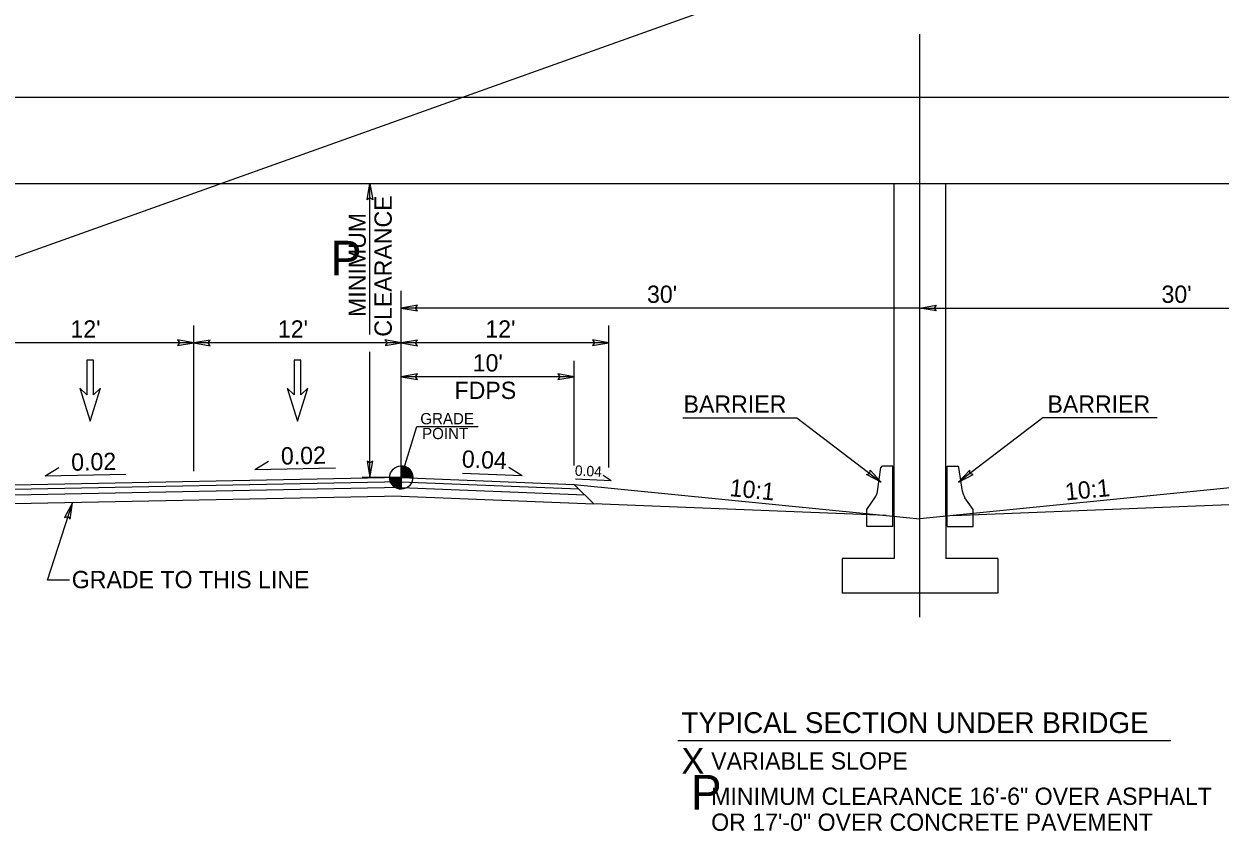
# Model space of a CAD drawing. Extents: x 1553195 to 1553792, y 810516 to 810787.
# Drawn here: x 1553492.4 to 1553561.6, y 810516 to 810562.7 of the extents above; entities that cross this region are included whole.
import ezdxf

# ---------------------------------------------------------------- set-up
doc = ezdxf.new("R2010")
doc.units = 0
for name, color, linetype in [('Old_Level_11', 7, 'Continuous'), ('Prop Dimension', 7, 'Continuous'), ('Prop DSN Text', 7, 'Continuous'), ('Prop Pavement Schedule Description CELL', 7, 'Continuous'), ('Prop Typical Section', 7, 'Continuous'), ('Sheet Sticker Incomplete CELL', 7, 'Continuous'), ('Typical Arrow Superelevation CELL', 7, 'Continuous'), ('Typical Pavement Slope CELL', 7, 'Continuous'), ('Typical Shoulder Slope CELL', 7, 'Continuous'), ('Typical Text ID Circle CELL', 7, 'Continuous'), ('z - Construction', 7, 'Continuous')]:
    doc.layers.add(name, color=color, linetype=linetype)

msp = doc.modelspace()

# ---------------------------------------------------------------- linework, layer by layer
at = {"layer": 'Old_Level_11'}
for p, q in [((1553514.206, 810536.478), (1553514.206, 810537.149)), ((1553513.535, 810536.478), (1553514.206, 810536.478)), ((1553514.205, 810535.806), (1553514.206, 810536.478)), ((1553514.206, 810536.478), (1553514.205, 810535.806)), ((1553514.878, 810536.478), (1553514.206, 810536.478))]:
    msp.add_line(p, q, dxfattribs=at)
for points in [[(1553514.212, 810537.149), (1553514.212, 810537.149), (1553514.212, 810536.478)], [(1553514.226, 810537.149), (1553514.226, 810536.478)], [(1553514.239, 810537.148), (1553514.239, 810536.478)], [(1553514.253, 810537.148), (1553514.253, 810536.478)], [(1553514.266, 810537.146), (1553514.266, 810536.478)], [(1553514.28, 810537.145), (1553514.28, 810536.478)], [(1553514.293, 810537.143), (1553514.293, 810536.478)], [(1553514.306, 810537.142), (1553514.306, 810536.478)], [(1553514.32, 810537.14), (1553514.32, 810536.478)], [(1553514.333, 810537.137), (1553514.333, 810536.478)], [(1553514.347, 810537.134), (1553514.347, 810536.478)], [(1553514.36, 810537.131), (1553514.36, 810536.478)], [(1553514.374, 810537.128), (1553514.374, 810536.478)], [(1553514.387, 810537.124), (1553514.387, 810536.478)], [(1553514.4, 810537.121), (1553514.4, 810536.478)], [(1553514.414, 810537.116), (1553514.414, 810536.478)], [(1553514.427, 810537.112), (1553514.427, 810536.478)], [(1553514.441, 810537.107), (1553514.441, 810536.478)], [(1553514.454, 810537.101), (1553514.454, 810536.478)], [(1553514.468, 810537.096), (1553514.468, 810536.478)], [(1553514.481, 810537.089), (1553514.481, 810536.478)], [(1553514.494, 810537.084), (1553514.494, 810536.478)], [(1553514.508, 810537.078), (1553514.508, 810536.478)], [(1553514.521, 810537.07), (1553514.521, 810536.478)], [(1553514.535, 810537.063), (1553514.535, 810536.478)], [(1553514.548, 810537.055), (1553514.548, 810536.478)], [(1553514.562, 810537.048), (1553514.562, 810536.478)], [(1553514.575, 810537.039), (1553514.575, 810536.478)], [(1553514.588, 810537.03), (1553514.588, 810536.478)], [(1553514.602, 810537.019), (1553514.602, 810536.478)], [(1553514.615, 810537.01), (1553514.615, 810536.478)], [(1553514.629, 810537), (1553514.629, 810536.478)], [(1553514.642, 810536.988), (1553514.642, 810536.478)], [(1553514.655, 810536.976), (1553514.655, 810536.478)], [(1553514.669, 810536.964), (1553514.669, 810536.478)], [(1553514.682, 810536.951), (1553514.682, 810536.478)], [(1553514.696, 810536.937), (1553514.696, 810536.478)], [(1553514.709, 810536.922), (1553514.709, 810536.478)], [(1553514.723, 810536.906), (1553514.723, 810536.478)], [(1553514.736, 810536.89), (1553514.736, 810536.478)], [(1553514.75, 810536.872), (1553514.75, 810536.478)], [(1553514.763, 810536.852), (1553514.763, 810536.478)], [(1553514.776, 810536.831), (1553514.776, 810536.478)], [(1553514.79, 810536.809), (1553514.79, 810536.478)], [(1553514.803, 810536.785), (1553514.803, 810536.478)], [(1553514.817, 810536.757), (1553514.817, 810536.478)], [(1553514.83, 810536.725), (1553514.83, 810536.478)], [(1553514.843, 810536.688), (1553514.843, 810536.478)], [(1553514.857, 810536.642), (1553514.857, 810536.478)], [(1553514.87, 810536.573), (1553514.87, 810536.478)], [(1553513.538, 810536.478), (1553513.538, 810536.405)], [(1553513.551, 810536.478), (1553513.551, 810536.326)], [(1553513.565, 810536.478), (1553513.565, 810536.278)], [(1553513.578, 810536.478), (1553513.578, 810536.238)], [(1553513.592, 810536.478), (1553513.592, 810536.206)], [(1553513.605, 810536.478), (1553513.605, 810536.178)], [(1553513.619, 810536.478), (1553513.619, 810536.153)], [(1553513.632, 810536.478), (1553513.632, 810536.129)], [(1553513.645, 810536.478), (1553513.645, 810536.108)], [(1553513.659, 810536.478), (1553513.659, 810536.088)], [(1553513.672, 810536.478), (1553513.672, 810536.071)], [(1553513.686, 810536.478), (1553513.686, 810536.054)], [(1553513.699, 810536.478), (1553513.699, 810536.038)], [(1553513.713, 810536.478), (1553513.713, 810536.023)], [(1553513.726, 810536.478), (1553513.726, 810536.008)], [(1553513.739, 810536.478), (1553513.739, 810535.994)], [(1553513.753, 810536.478), (1553513.753, 810535.982)], [(1553513.766, 810536.478), (1553513.766, 810535.971)], [(1553513.78, 810536.478), (1553513.78, 810535.959)], [(1553513.793, 810536.478), (1553513.793, 810535.948)], [(1553513.807, 810536.478), (1553513.807, 810535.938)], [(1553513.82, 810536.478), (1553513.82, 810535.929)], [(1553513.833, 810536.478), (1553513.833, 810535.92)], [(1553513.847, 810536.478), (1553513.847, 810535.911)], [(1553513.86, 810536.478), (1553513.86, 810535.902)], [(1553513.874, 810536.478), (1553513.874, 810535.894)], [(1553513.887, 810536.478), (1553513.887, 810535.887)], [(1553513.901, 810536.478), (1553513.901, 810535.88)], [(1553513.914, 810536.478), (1553513.914, 810535.874)], [(1553513.927, 810536.478), (1553513.927, 810535.868)], [(1553513.941, 810536.478), (1553513.941, 810535.862)], [(1553513.954, 810536.478), (1553513.954, 810535.856)], [(1553513.968, 810536.478), (1553513.968, 810535.85)], [(1553513.981, 810536.478), (1553513.981, 810535.845)], [(1553513.995, 810536.478), (1553513.995, 810535.841)], [(1553514.008, 810536.478), (1553514.008, 810535.836)], [(1553514.021, 810536.478), (1553514.021, 810535.833)], [(1553514.035, 810536.478), (1553514.035, 810535.829)], [(1553514.048, 810536.478), (1553514.048, 810535.826)], [(1553514.062, 810536.478), (1553514.062, 810535.823)], [(1553514.075, 810536.478), (1553514.075, 810535.82)], [(1553514.089, 810536.478), (1553514.089, 810535.817)], [(1553514.102, 810536.478), (1553514.102, 810535.815)], [(1553514.115, 810536.478), (1553514.115, 810535.812)], [(1553514.129, 810536.478), (1553514.129, 810535.811)], [(1553514.142, 810536.478), (1553514.142, 810535.809)], [(1553514.156, 810536.478), (1553514.156, 810535.808)], [(1553514.169, 810536.478), (1553514.169, 810535.808)], [(1553514.183, 810536.478), (1553514.183, 810535.806)], [(1553514.196, 810536.478), (1553514.196, 810535.806), (1553514.196, 810535.806)]]:
    msp.add_lwpolyline(points, dxfattribs=at)
msp.add_circle((1553514.206, 810536.478), 0.671, dxfattribs=at)
for start, end in [(359.99048, 89.99048), (179.99048, 269.99048)]:
    msp.add_arc((1553514.206, 810536.478), 0.671, start, end, dxfattribs=at)
at = {"layer": 'Prop Dimension'}
for p, q in [((1553505.739, 810536.942), (1553506.522, 810537.415)), ((1553493.608, 810536.58), (1553494.391, 810537.054)), ((1553493.608, 810536.58), (1553498.268, 810536.674)), ((1553505.739, 810536.942), (1553510.4, 810537.035)), ((1553521.206, 810536.574), (1553517.756, 810536.712)), ((1553521.206, 810536.574), (1553520.433, 810537.063)), ((1553526.345, 810536.293), (1553525.881, 810536.586)), ((1553526.345, 810536.293), (1553524.275, 810536.375))]:
    msp.add_line(p, q, dxfattribs=at)
at = {"layer": 'Prop DSN Text'}
for points in [[(1553512.235, 810552.541), (1553512.396, 810553.478), (1553512.563, 810552.535), (1553512.396, 810552.655)], [(1553515.143, 810546.438), (1553514.206, 810546.277), (1553515.148, 810546.11), (1553515.028, 810546.277)], [(1553545.143, 810546.115), (1553544.206, 810546.277), (1553545.148, 810546.443), (1553545.028, 810546.277)], [(1553501.268, 810544.103), (1553502.206, 810544.264), (1553501.263, 810544.431), (1553501.383, 810544.264)], [(1553503.143, 810544.426), (1553502.206, 810544.264), (1553503.148, 810544.098), (1553503.028, 810544.264)], [(1553513.268, 810544.103), (1553514.206, 810544.264), (1553513.263, 810544.431), (1553513.383, 810544.264)], [(1553515.143, 810544.426), (1553514.206, 810544.264), (1553515.148, 810544.098), (1553515.028, 810544.264)], [(1553525.268, 810544.103), (1553526.206, 810544.264), (1553525.263, 810544.431), (1553525.383, 810544.264)], [(1553515.143, 810542.47), (1553514.206, 810542.309), (1553515.148, 810542.142), (1553515.028, 810542.309)], [(1553523.268, 810542.147), (1553524.206, 810542.309), (1553523.263, 810542.476), (1553523.383, 810542.309)], [(1553512.235, 810537.415), (1553512.396, 810536.478), (1553512.563, 810537.421), (1553512.396, 810537.301)], [(1553541.324, 810536.904), (1553541.972, 810536.207), (1553541.121, 810536.646), (1553541.317, 810536.706)], [(1553547.087, 810536.904), (1553546.439, 810536.207), (1553547.29, 810536.646), (1553547.094, 810536.706)], [(1553495.046, 810534.072), (1553495.179, 810535.014), (1553494.732, 810534.168), (1553494.927, 810534.231)]]:
    msp.add_lwpolyline(points, close=True, dxfattribs=at)
at = {"layer": 'Prop Pavement Schedule Description CELL'}
for p, q in [((1553493.738, 810530.531), (1553495.179, 810535.014)), ((1553495.021, 810530.531), (1553493.738, 810530.531)), ((1553530.204, 810521.277), (1553558.722, 810521.277))]:
    msp.add_line(p, q, dxfattribs=at)
at = {"layer": 'Prop Typical Section'}
msp.add_line((1553544.206, 810528.399), (1553544.206, 810562.118), dxfattribs=at)
for points in [[(1553496.799, 810541.639), (1553496.393, 810541.264), (1553496.393, 810543.264), (1553496.018, 810543.264), (1553496.018, 810541.264), (1553495.612, 810541.639), (1553496.206, 810539.733)], [(1553496.799, 810541.639), (1553496.393, 810541.264), (1553496.393, 810543.264), (1553496.018, 810543.264), (1553496.018, 810541.264), (1553495.612, 810541.639), (1553496.206, 810539.733)], [(1553508.799, 810541.639), (1553508.393, 810541.264), (1553508.393, 810543.264), (1553508.018, 810543.264), (1553508.018, 810541.264), (1553507.612, 810541.639), (1553508.206, 810539.733)], [(1553508.799, 810541.639), (1553508.393, 810541.264), (1553508.393, 810543.264), (1553508.018, 810543.264), (1553508.018, 810541.264), (1553507.612, 810541.639), (1553508.206, 810539.733)]]:
    msp.add_lwpolyline(points, close=True, dxfattribs=at)
at = {"layer": 'Sheet Sticker Incomplete CELL'}
for p, q in [((1553524.206, 810536.078), (1553544.206, 810534.078)), ((1553564.206, 810536.078), (1553544.206, 810534.078)), ((1553542.261, 810534.272), (1553525.334, 810534.95)), ((1553546.15, 810534.272), (1553563.077, 810534.95))]:
    msp.add_line(p, q, dxfattribs=at)
at = {"layer": 'Typical Arrow Superelevation CELL'}
for p, q in [((1553652.472, 810606.601), (1553448.543, 810533.73)), ((1553446.448, 810558.478), (1553641.963, 810558.478)), ((1553446.448, 810553.478), (1553641.963, 810553.478)), ((1553542.706, 810534.228), (1553542.706, 810553.478)), ((1553545.706, 810534.228), (1553545.706, 810553.478)), ((1553542.706, 810534.228), (1553542.706, 810531.795)), ((1553545.706, 810534.228), (1553545.706, 810531.795)), ((1553542.706, 810531.795), (1553539.706, 810531.795)), ((1553539.706, 810531.795), (1553539.706, 810529.795)), ((1553548.706, 810531.795), (1553545.706, 810531.795)), ((1553548.706, 810531.795), (1553548.706, 810529.795)), ((1553548.706, 810529.795), (1553539.706, 810529.795))]:
    msp.add_line(p, q, dxfattribs=at)
at = {"layer": 'Typical Pavement Slope CELL'}
for p, q in [((1553514.206, 810536.478), (1553490.206, 810535.998)), ((1553514.206, 810536.228), (1553490.206, 810535.748)), ((1553514.206, 810535.895), (1553490.206, 810535.415)), ((1553514.206, 810536.478), (1553524.206, 810536.078)), ((1553514.206, 810536.228), (1553524.466, 810535.818)), ((1553514.206, 810535.895), (1553524.813, 810535.47)), ((1553524.206, 810536.078), (1553525.334, 810534.95)), ((1553514.206, 810535.395), (1553490.206, 810534.915)), ((1553514.206, 810535.395), (1553525.334, 810534.95))]:
    msp.add_line(p, q, dxfattribs=at)
at = {"layer": 'Typical Shoulder Slope CELL'}
for points in [[(1553541.743, 810535.663), (1553541.953, 810537.065)], [(1553542.631, 810533.635), (1553542.631, 810537.135), (1553542.036, 810537.135)], [(1553545.781, 810533.635), (1553545.781, 810537.135), (1553546.376, 810537.135)], [(1553546.668, 810535.663), (1553546.458, 810537.065)], [(1553542.631, 810533.635), (1553541.131, 810533.635), (1553541.131, 810534.385), (1553541.131, 810534.635), (1553541.602, 810535.308)], [(1553545.781, 810533.635), (1553547.281, 810533.635), (1553547.281, 810534.385), (1553547.281, 810534.635), (1553546.81, 810535.308)]]:
    msp.add_lwpolyline(points, dxfattribs=at)
for centre, radius, start, end in [((1553542.036, 810537.052), 0.0833, 90, 171.46923), ((1553546.376, 810537.052), 0.0833, 8.53077, 90), ((1553540.919, 810535.786), 0.833, 325.00798, 351.46923), ((1553547.492, 810535.786), 0.833, 188.53077, 214.99202)]:
    msp.add_arc(centre, radius, start, end, dxfattribs=at)
at = {"layer": 'Typical Text ID Circle CELL'}
msp.add_lwpolyline([(1553514.206, 810536.478), (1553515.109, 810539.432), (1553518.647, 810539.432)], dxfattribs=at)
at = {"layer": 'z - Construction'}
for p, q in [((1553512.396, 810544.746), (1553512.396, 810553.478)), ((1553514.206, 810537.167), (1553514.206, 810547.267)), ((1553544.206, 810546.277), (1553514.206, 810546.277)), ((1553544.206, 810546.277), (1553574.206, 810546.277)), ((1553502.206, 810536.841), (1553502.206, 810545.264)), ((1553526.206, 810537.049), (1553526.206, 810545.264)), ((1553502.206, 810544.264), (1553490.206, 810544.264)), ((1553514.206, 810544.264), (1553502.206, 810544.264)), ((1553526.206, 810544.264), (1553514.206, 810544.264)), ((1553512.396, 810536.478), (1553512.396, 810543.752)), ((1553524.206, 810537.167), (1553524.206, 810543.223)), ((1553524.206, 810542.309), (1553514.206, 810542.309)), ((1553514.206, 810536.478), (1553511.943, 810536.478))]:
    msp.add_line(p, q, dxfattribs=at)
for points in [[(1553530.485, 810539.922), (1553537.093, 810539.922), (1553541.972, 810536.207)], [(1553557.927, 810539.922), (1553551.318, 810539.922), (1553546.439, 810536.207)]]:
    msp.add_lwpolyline(points, dxfattribs=at)

# ---------------------------------------------------------------- texts
at = {"layer": 'Prop Pavement Schedule Description CELL'}
for s, height, rotation, p in [('CLEARANCE', 1, 90, (1553513.655, 810544.618)), ('MINIMUM', 1, 90, (1553512.155, 810545.761)), ('0.02', 1, 1.14587, (1553495.122, 810536.864)), ('0.02', 1, 1.14587, (1553507.253, 810537.225)), ('0.04', 1, 357.70939, (1553517.693, 810537.057)), ('0.04', 0.6, 357.70939, (1553524.237, 810536.582)), ('10:1', 1, 354.28941, (1553533.164, 810535.407)), ('10:1', 1, 5.71059, (1553552.648, 810535.147))]:
    msp.add_text(s, height=height, rotation=rotation, dxfattribs=at).set_placement(p)
for s, height, p in [('P', 2, (1553510.123, 810548.165)), ("30'", 1, (1553528.419, 810546.577)), ("30'", 1, (1553558.179, 810546.577)), ("12'", 1, (1553495.068, 810544.565)), ("12'", 1, (1553507.068, 810544.565)), ("12'", 1, (1553519.068, 810544.565)), ("10'", 1, (1553518.338, 810542.609)), ('FDPS', 1, (1553517.286, 810541.019)), ('BARRIER', 1, (1553530.534, 810540.223)), ('BARRIER', 1, (1553551.582, 810540.223)), ('GRADE TO THIS LINE', 1, (1553495.147, 810530.074)), ('TYPICAL SECTION UNDER BRIDGE', 1.2, (1553530.415, 810521.703)), ('X', 1.5, (1553530.403, 810519.342)), ('VARIABLE SLOPE', 1, (1553532.131, 810519.587)), ('P', 2, (1553530.949, 810517.272)), ('MINIMUM CLEARANCE 16\'-6" OVER ASPHALT', 1, (1553532.131, 810517.544)), ('OR 17\'-0" OVER CONCRETE PAVEMENT', 1, (1553532.131, 810516.044))]:
    msp.add_text(s, height=height, dxfattribs=at).set_placement(p)
at = {"layer": 'Typical Text ID Circle CELL'}
for s, p in [('GRADE', (1553515.306, 810539.554)), ('POINT', (1553515.409, 810538.696))]:
    msp.add_text(s, height=0.6525, dxfattribs=at).set_placement(p)

doc.saveas('drawing.dxf')
